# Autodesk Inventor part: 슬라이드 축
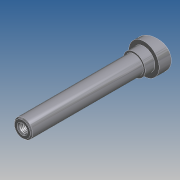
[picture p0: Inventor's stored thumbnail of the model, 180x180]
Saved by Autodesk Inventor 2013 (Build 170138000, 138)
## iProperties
Company: 한국ATC센터
Created: 2014-07
Part Number: 슬라이드 축
Document SubType Name: 모델링
Designer: KYOUNG IL JANG
Mass: 21.572 g
Surface Area: 67.5858 cm^2
Volume: 21.572 cm^3
Density: 1 g/cm^3
Material: Generic
변환 표준: STEP AP214IS
파일 이름: C:\Users\SeoGD\Desktop\?쒗뿕\異?stp
전처리기: Build: 253, Release: 2010 SP1 - Date: Wed 07/29/2009
전송 단위: 밀리미터
불확실성: 0.01
Author: KYOUNG IL JANG
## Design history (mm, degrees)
revolve "회전1" stored, may be unused: angle "d4" = 90 deg
sketch "스케치2"
  geometry: L1 (12.5, 0)-(12.5, -17) reference; L2 (-12.5, -17)-(12.5, -17) reference; L3 (-12.5, 0)-(-12.5, -17) reference; L4 (12.5, -5)-(-12.5, -11.699); L5 (-12.5, 0)-(12.5, 0) reference; 1 further point
  constraints: 2 end point, 2 point on line
  dimensions: "d5" = 75 deg angle of L1 L4; "d6" = 5 distance from line of L4.start L5
extrude "돌출1" cut sketch "스케치2" stored distance "d7" = 10; taper "d8" = 0 deg
chamfer "모따기1" distance "d9" = 1; stored, may be unused: second distance "d10" = 2, angle "d11" = 45 deg
fillet "모깎기1" dims "d12" = 0.5
hole "구멍1" diameter "d15" = 6.647; stored, may be unused: countersink angle "d19" = 90 deg, drill point angle "d21" = 118 deg; dims "d13" = 10, "d14" = 10, "d16" = 17, "d17" = 4, "d18" = 2, "d20" = 20
chamfer "모따기2" distance "d22" = 1; stored, may be unused: second distance "d23" = 2, angle "d24" = 45 deg
sketch "스케치3"
  geometry: C1 r 9 at (0, 0); 1 further point
  constraints: 1 centre point, 1 coincident
  dimensions: "d25" = 18 diameter of C1
extrude "돌출2" join sketch "스케치3" distance "d26" = 8; taper "d27" = 0 deg
node "솔리드1"
node "솔리드 본체"
node "곡면 본체"
sketch "스케치1"
  geometry: L1 (0, 100)-(7.5, 100); L2 (7.5, 100)-(7.5, 0); L3 (7.5, 0)-(12.5, 0); L4 (12.5, 0)-(12.5, -17); L5 (12.5, -17)-(0, -17); L6 (0, -17)-(0, 100); 1 further point
  constraints: 12 end point, 2 parallel, 2 point on line, 1 perpendicular, 1 vertical
  dimensions: "d0" = 100 distance from line of L1 point (0, 0); "d1" = 15 diameter of L2 L6; "d2" = 25 diameter of L4 L6; "d3" = 17 distance of L3.end L4.end
node "솔리드2"
